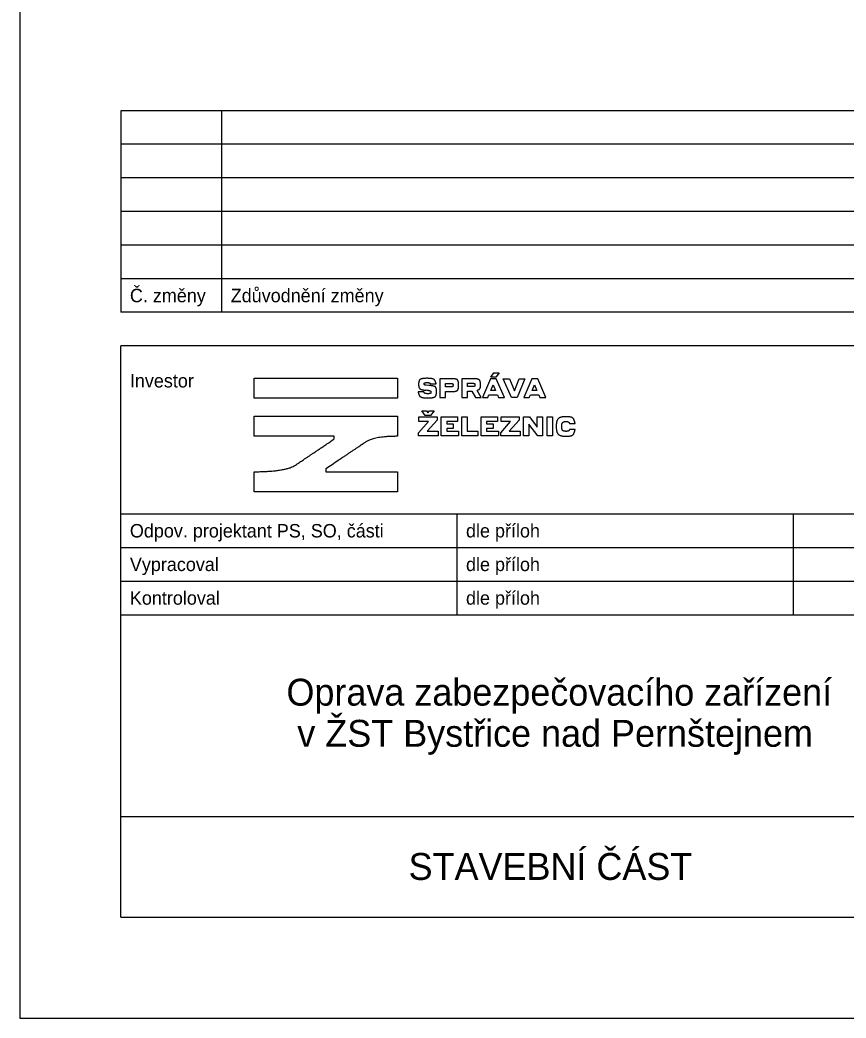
# Model space of a CAD drawing. Extents: x -790471 to -790261, y -988964 to -988667.
# Drawn here: x -790470.6 to -790347.7, y -988964.2 to -988815.7 of the extents above; entities that cross this region are included whole.
import ezdxf

# ---------------------------------------------------------------- set-up
doc = ezdxf.new("R2010")
doc.units = 0
for name, color, linetype in [('logo_sprava_zeleznic', 7, 'Continuous'), ('Ramečky', 7, 'Continuous'), ('Rámečky-tisk', 7, 'Continuous'), ('Text', 7, 'Continuous'), ('Text barevný', 7, 'Continuous')]:
    doc.layers.add(name, color=color, linetype=linetype)

msp = doc.modelspace()

# ---------------------------------------------------------------- linework, layer by layer
at = {"layer": 'logo_sprava_zeleznic'}
for p, q in [((-790400.56, -988868.85), (-790400.12, -988868.19)), ((-790399.78, -988868.85), (-790400.56, -988868.85)), ((-790400.12, -988868.19), (-790399.3, -988868.19)), ((-790399.3, -988868.19), (-790399.78, -988868.85)), ((-790409.76, -988870.07), (-790410.15, -988870.04)), ((-790409.51, -988869.82), (-790408.69, -988869.82)), ((-790398.7, -988869.07), (-790397.76, -988869.07)), ((-790397.49, -988871.88), (-790398.7, -988869.07)), ((-790397.76, -988869.07), (-790397.05, -988870.87)), ((-790397.05, -988870.87), (-790396.34, -988869.07)), ((-790395.49, -988869.07), (-790396.64, -988871.88)), ((-790396.34, -988869.07), (-790395.49, -988869.07)), ((-790410.51, -988871.04), (-790411.36, -988871.04)), ((-790396.64, -988871.88), (-790397.49, -988871.88)), ((-790411.26, -988874.76), (-790408.55, -988874.76)), ((-790411.26, -988875.45), (-790411.26, -988874.76)), ((-790410.29, -988874.55), (-790410.83, -988873.87)), ((-790410.83, -988873.87), (-790410.14, -988873.87)), ((-790409.53, -988874.55), (-790410.29, -988874.55)), ((-790410.14, -988873.87), (-790409.91, -988874.16)), ((-790409.91, -988874.16), (-790409.68, -988873.87)), ((-790409.68, -988873.87), (-790408.97, -988873.87)), ((-790408.97, -988873.87), (-790409.53, -988874.55)), ((-790408.55, -988874.76), (-790408.55, -988875.22)), ((-790407.92, -988874.76), (-790405.49, -988874.76)), ((-790407.92, -988877.58), (-790407.92, -988874.76)), ((-790405.49, -988874.76), (-790405.49, -988875.42)), ((-790404.86, -988874.76), (-790404.05, -988874.76)), ((-790404.86, -988877.58), (-790404.86, -988874.76)), ((-790404.05, -988874.76), (-790404.05, -988876.87)), ((-790401.99, -988874.76), (-790399.57, -988874.76)), ((-790401.99, -988877.58), (-790401.99, -988874.76)), ((-790399.57, -988874.76), (-790399.57, -988875.42)), ((-790399.03, -988874.76), (-790396.33, -988874.76)), ((-790399.03, -988875.45), (-790399.03, -988874.76)), ((-790396.33, -988874.76), (-790396.33, -988875.22)), ((-790395.69, -988874.76), (-790394.78, -988874.76)), ((-790395.69, -988877.58), (-790395.69, -988874.76)), ((-790394.78, -988874.76), (-790393.63, -988876.27)), ((-790393.63, -988876.27), (-790393.63, -988874.76)), ((-790393.63, -988874.76), (-790392.85, -988874.76)), ((-790392.85, -988874.76), (-790392.85, -988877.58)), ((-790411.3, -988877.12), (-790409.84, -988875.45)), ((-790409.84, -988875.45), (-790411.26, -988875.45)), ((-790408.55, -988875.22), (-790410.02, -988876.88)), ((-790405.49, -988875.42), (-790407.1, -988875.42)), ((-790407.1, -988875.42), (-790407.1, -988875.79)), ((-790407.1, -988875.79), (-790406.14, -988875.79)), ((-790406.14, -988875.79), (-790406.14, -988876.46)), ((-790399.57, -988875.42), (-790401.18, -988875.42)), ((-790401.18, -988875.42), (-790401.18, -988875.79)), ((-790401.18, -988875.79), (-790400.22, -988875.79)), ((-790400.22, -988875.79), (-790400.22, -988876.46)), ((-790399.07, -988877.12), (-790397.61, -988875.45)), ((-790397.61, -988875.45), (-790399.03, -988875.45)), ((-790396.33, -988875.22), (-790397.8, -988876.88)), ((-790393.53, -988877.58), (-790394.89, -988875.85)), ((-790394.89, -988875.85), (-790394.89, -988877.58)), ((-790388.84, -988875.71), (-790388.01, -988875.71)), ((-790411.3, -988877.58), (-790411.3, -988877.12)), ((-790408.39, -988877.58), (-790411.3, -988877.58)), ((-790410.02, -988876.88), (-790408.39, -988876.88)), ((-790408.39, -988876.88), (-790408.39, -988877.58)), ((-790405.34, -988877.58), (-790407.92, -988877.58)), ((-790406.14, -988876.46), (-790407.1, -988876.46)), ((-790407.1, -988876.46), (-790407.1, -988876.89)), ((-790407.1, -988876.89), (-790405.34, -988876.89)), ((-790405.34, -988876.89), (-790405.34, -988877.58)), ((-790402.47, -988877.58), (-790404.86, -988877.58)), ((-790404.05, -988876.87), (-790402.47, -988876.87)), ((-790402.47, -988876.87), (-790402.47, -988877.58)), ((-790399.41, -988877.58), (-790401.99, -988877.58)), ((-790400.22, -988876.46), (-790401.18, -988876.46)), ((-790401.18, -988876.46), (-790401.18, -988876.89)), ((-790401.18, -988876.89), (-790399.41, -988876.89)), ((-790399.41, -988876.89), (-790399.41, -988877.58)), ((-790399.07, -988877.58), (-790399.07, -988877.12)), ((-790396.16, -988877.58), (-790399.07, -988877.58)), ((-790397.8, -988876.88), (-790396.16, -988876.88)), ((-790396.16, -988876.88), (-790396.16, -988877.58)), ((-790394.89, -988877.58), (-790395.69, -988877.58)), ((-790392.85, -988877.58), (-790393.53, -988877.58)), ((-790388.01, -988876.64), (-790388.83, -988876.64))]:
    msp.add_line(p, q, dxfattribs=at)
for points in [[(-790435.73, -988868.99), (-790414.41, -988868.99), (-790414.41, -988871.97), (-790435.73, -988871.97)], [(-790401.8, -988871.88), (-790400.98, -988871.88), (-790400.82, -988871.49), (-790399.57, -988871.49), (-790399.41, -988871.88), (-790398.53, -988871.88), (-790399.73, -988869.07), (-790400.6, -988869.07)], [(-790400.19, -988869.98), (-790399.85, -988870.82), (-790400.54, -988870.82)], [(-790395.65, -988871.88), (-790394.83, -988871.88), (-790394.66, -988871.49), (-790393.42, -988871.49), (-790393.26, -988871.88), (-790392.38, -988871.88), (-790393.57, -988869.07), (-790394.45, -988869.07)], [(-790394.04, -988869.98), (-790393.7, -988870.82), (-790394.39, -988870.82)], [(-790392.16, -988874.76), (-790391.35, -988874.76), (-790391.35, -988877.58), (-790392.16, -988877.58)]]:
    msp.add_lwpolyline(points, close=True, dxfattribs=at)
for points in [[(-790406.38, -988869.07), (-790408.11, -988869.07), (-790408.11, -988871.88), (-790407.3, -988871.88), (-790407.3, -988870.98), (-790406.38, -988870.98)], [(-790406.48, -988870.28), (-790407.3, -988870.28), (-790407.3, -988869.77), (-790406.48, -988869.77)], [(-790403.12, -988869.07), (-790404.84, -988869.07), (-790404.84, -988871.88), (-790404.03, -988871.88), (-790404.03, -988870.9), (-790403.39, -988870.9), (-790402.84, -988871.88), (-790401.98, -988871.88), (-790402.59, -988870.81)], [(-790403.22, -988870.23), (-790404.03, -988870.23), (-790404.03, -988869.75), (-790403.22, -988869.75)], [(-790423.87, -988878.05), (-790423.87, -988877.64), (-790435.73, -988877.64), (-790435.73, -988874.66), (-790414.41, -988874.66), (-790414.41, -988877.64)], [(-790425.1, -988882.5), (-790425.1, -988882.91), (-790414.41, -988882.91), (-790414.41, -988885.89), (-790435.73, -988885.89), (-790435.73, -988882.91), (-790435.71, -988882.91)]]:
    msp.add_lwpolyline(points, dxfattribs=at)
for centre, radius, start, end in [((-790411.9, -988891.73), 21.01, 84.2634, 85.3384), ((-790461.18, -988825.19), 64.69, 304.0901, 305.2133), ((-790124.63, -989319.13), 530.02, 124.292, 124.5333)]:
    msp.add_arc(centre, radius, start, end, dxfattribs=at)
for points in [[(-790410.05, -988869.01), (-790410.77, -988869.01), (-790411.29, -988869.3), (-790411.29, -988869.88)], [(-790411.29, -988869.88), (-790411.29, -988870.42), (-790410.87, -988870.73), (-790410.19, -988870.79)], [(-790410.46, -988869.84), (-790410.46, -988869.71), (-790410.3, -988869.65), (-790410.05, -988869.65)], [(-790410.15, -988870.04), (-790410.35, -988870.02), (-790410.46, -988869.95), (-790410.46, -988869.84)], [(-790408.69, -988869.82), (-790408.77, -988869.46), (-790409.09, -988869.01), (-790410.05, -988869.01)], [(-790410.05, -988869.65), (-790409.73, -988869.65), (-790409.55, -988869.76), (-790409.51, -988869.82)], [(-790408.63, -988870.99), (-790408.63, -988870.38), (-790409.03, -988870.13), (-790409.76, -988870.07)], [(-790406.48, -988869.77), (-790406.27, -988869.77), (-790406.17, -988869.85), (-790406.17, -988870.02)], [(-790406.17, -988870.02), (-790406.17, -988870.19), (-790406.27, -988870.28), (-790406.48, -988870.28)], [(-790405.34, -988870.02), (-790405.34, -988869.39), (-790405.73, -988869.07), (-790406.38, -988869.07)], [(-790406.38, -988870.98), (-790405.73, -988870.98), (-790405.34, -988870.65), (-790405.34, -988870.02)], [(-790403.22, -988869.75), (-790403.02, -988869.75), (-790402.91, -988869.82), (-790402.91, -988869.99)], [(-790402.91, -988869.99), (-790402.91, -988870.14), (-790403.02, -988870.23), (-790403.22, -988870.23)], [(-790402.08, -988869.99), (-790402.08, -988869.38), (-790402.49, -988869.07), (-790403.12, -988869.07)], [(-790402.59, -988870.81), (-790402.27, -988870.67), (-790402.08, -988870.39), (-790402.08, -988869.99)], [(-790411.36, -988871.04), (-790411.29, -988871.43), (-790410.93, -988871.93), (-790409.92, -988871.93)], [(-790409.92, -988871.3), (-790410.28, -988871.3), (-790410.46, -988871.16), (-790410.51, -988871.04)], [(-790409.92, -988871.93), (-790409.08, -988871.93), (-790408.63, -988871.59), (-790408.63, -988870.99)], [(-790409.47, -988871.05), (-790409.47, -988871.2), (-790409.6, -988871.3), (-790409.92, -988871.3)], [(-790409.8, -988870.82), (-790409.6, -988870.85), (-790409.47, -988870.9), (-790409.47, -988871.05)], [(-790389.36, -988874.72), (-790390.22, -988874.72), (-790390.82, -988875.32), (-790390.82, -988876.17)], [(-790388.01, -988875.71), (-790388.06, -988875.39), (-790388.4, -988874.72), (-790389.36, -988874.72)], [(-790390.82, -988876.17), (-790390.82, -988877.02), (-790390.22, -988877.63), (-790389.36, -988877.63)], [(-790390, -988876.17), (-790390, -988875.77), (-790389.76, -988875.44), (-790389.36, -988875.44)], [(-790389.36, -988876.9), (-790389.76, -988876.9), (-790390, -988876.58), (-790390, -988876.17)], [(-790389.36, -988875.44), (-790389.02, -988875.44), (-790388.88, -988875.64), (-790388.84, -988875.71)], [(-790414.41, -988877.64), (-790417.9, -988877.64), (-790420.38, -988879.31), (-790423.25, -988881.24)], [(-790389.36, -988877.63), (-790388.37, -988877.63), (-790388.05, -988876.9), (-790388.01, -988876.64)], [(-790388.83, -988876.64), (-790388.87, -988876.71), (-790389.02, -988876.9), (-790389.36, -988876.9)], [(-790435.71, -988882.91), (-790431.06, -988882.9), (-790428.08, -988880.9), (-790424.92, -988878.77)]]:
    msp.add_open_spline(points, degree=2, dxfattribs=at)
at = {"layer": 'Ramečky'}
for p, q in [((-790275.59, -988829.19), (-790455.59, -988829.19)), ((-790455.59, -988829.19), (-790455.59, -988859.19)), ((-790440.59, -988829.19), (-790440.59, -988859.19)), ((-790305.59, -988834.19), (-790455.59, -988834.19)), ((-790305.59, -988839.19), (-790455.59, -988839.19)), ((-790305.59, -988844.19), (-790455.59, -988844.19)), ((-790305.59, -988849.19), (-790455.59, -988849.19)), ((-790305.59, -988854.19), (-790455.59, -988854.19)), ((-790275.59, -988859.19), (-790455.59, -988859.19)), ((-790275.59, -988864.19), (-790455.59, -988864.19)), ((-790455.59, -988949.19), (-790455.59, -988864.19)), ((-790455.59, -988889.19), (-790325.59, -988889.19)), ((-790455.59, -988894.19), (-790325.59, -988894.19)), ((-790455.59, -988899.19), (-790325.59, -988899.19)), ((-790455.59, -988904.19), (-790325.59, -988904.19)), ((-790455.59, -988934.19), (-790275.59, -988934.19)), ((-790455.59, -988949.19), (-790275.59, -988949.19))]:
    msp.add_line(p, q, dxfattribs=at)
for points in [[(-790405.59, -988889.19), (-790405.59, -988904.19)], [(-790355.59, -988889.19), (-790355.59, -988904.19)]]:
    msp.add_lwpolyline(points, dxfattribs=at)
at = {"layer": 'Rámečky-tisk'}
msp.add_line((-790470.59, -988667.19), (-790470.59, -988964.19), dxfattribs=at)
msp.add_lwpolyline([(-790470.59, -988964.19), (-790260.59, -988964.19), (-790260.59, -988667.19)], dxfattribs=at)

# ---------------------------------------------------------------- texts
at = {"layer": 'Text'}
for s, p in [('Č. změny', (-790454.24, -988857.69)), ('Zdůvodnění změny', (-790439.24, -988857.69)), ('Investor', (-790454.24, -988870.37)), ('Odpov. projektant PS, SO, části', (-790454.24, -988892.69)), ('dle příloh', (-790404.24, -988892.69)), ('Vypracoval', (-790454.24, -988897.69)), ('dle příloh', (-790404.24, -988897.69)), ('Kontroloval', (-790454.24, -988902.69)), ('dle příloh', (-790404.24, -988902.69))]:
    msp.add_text(s, height=2, dxfattribs=at).set_placement(p)
at = {"layer": 'Text barevný'}
for s, p in [('Oprava zabezpečovacího zařízení', (-790430.95, -988917.71)), ('v ŽST Bystřice nad Pernštejnem', (-790429.33, -988923.83)), ('STAVEBNÍ ČÁST', (-790412.78, -988943.64))]:
    msp.add_text(s, height=4, dxfattribs=at).set_placement(p)

doc.saveas('drawing.dxf')
